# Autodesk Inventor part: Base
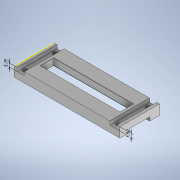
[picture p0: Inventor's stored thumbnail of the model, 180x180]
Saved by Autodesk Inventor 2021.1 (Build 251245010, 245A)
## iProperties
Created: 2020-12
Part Number: Base
Material: Generic
Document SubType Name: Modeling
Designer: BALA
Density: 1 g/cm^3
Appearance: Default
Author: BALA
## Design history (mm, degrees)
node "Annotations"
  node "Linear Dimension 1" dims "d4" = 10, "d5" = 60, "d6" = 4.5, "d7" = 10 (derived), "d87" = 5.25 (derived)
  node "Linear Dimension 2" dims "d4" = 10, "d5" = 60, "d6" = 4.5, "d7" = 10 (derived), "d88" = 5.5 (derived)
sketch "Sketch1"
  geometry: 1 further point
sketch "Sketch2"
  geometry: L1 (0, 0)-(160, 0); L2 (160, 0)-(160, 60); L3 (160, 60)-(0, 60); L4 (0, 60)-(0, 0)
  constraints: 8 end point, 2 parallel, 1 horizontal, 1 perpendicular
  dimensions: "d0" = 160 distance of L3.end L2.end; "d1" = 60 distance of L2.end L1.end
extrude "Extrusion1" new body sketch "Sketch2" distance "d2" = 15; taper "d3" = 0 deg
sketch "Sketch3"
  geometry: 1 further point
sketch "Sketch4"
  geometry: L1 (4.5, 0)-(14.5, 0); L2 (14.5, 0)-(14.5, 60); L3 (14.5, 60)-(4.5, 60); L4 (4.5, 60)-(4.5, 0); L5 (160, 60)-(0, 60) reference; L6 (80, 60)-(80, 0); L7 (0, 0)-(160, 0) reference; L8 (155.5, 0)-(145.5, 0); L9 (145.5, 0)-(145.5, 60); L10 (145.5, 60)-(155.5, 60); L11 (155.5, 60)-(155.5, 0)
  constraints: 18 end point, 4 symmetric about line, 2 midpoint, 2 parallel, 1 horizontal, 1 perpendicular
  dimensions: "d4" = 10 distance of L3.end L2.end; "d5" = 60 distance of L2.end L1.end; "d6" = 4.5 distance of L10.end L5.start; "d7" = 10 distance of L10.end L9.end (derived)
extrude "Extrusion2" cut sketch "Sketch4" distance "d8" = 5; taper "d9" = 0 deg
chamfer "Chamfer1" distance "d10" = 0.5; stored, may be unused: second distance "d11" = 2, angle "d12" = 45 deg
sketch "Sketch5"
  geometry: L1 (20, 20)-(20, 40); L2 (20, 40)-(140, 40); L3 (140, 40)-(140, 20); L4 (140, 20)-(20, 20); L5 (0, 60)-(0, 0) reference; L6 (160, 0)-(160, 60) reference
  constraints: 8 end point, 3 perpendicular, 1 vertical
  dimensions: "d13" = 20 distance from line of L1.end L5; "d17" = 20 distance from line of L6 L2.end; "d18" = 20 distance of L1.start L1.end
extrude "Extrusion3" cut sketch "Sketch5" distance "d19" = 15; taper "d20" = 0 deg
chamfer "Chamfer2" distance "d21" = 0.5; stored, may be unused: second distance "d22" = 2, angle "d23" = 45 deg
chamfer "Chamfer3" distance "d24" = 0.5; stored, may be unused: second distance "d25" = 2, angle "d26" = 45 deg
sketch "Sketch6"
  geometry: L1 (0, 60)-(0, 0) reference; L2 (0, 15)-(-160.097, 15); L3 (-160.097, 15)-(-160.097, 45); L4 (-160.097, 45)-(0, 45); L5 (0, 45)-(0, 15); 1 further point
  constraints: 8 end point, 2 parallel, 1 horizontal, 1 perpendicular, 1 point on line
  dimensions: "d27" = 15 distance of L2.start L1.end; "d28" = 15 distance of L4.end L1.start
extrude "Extrusion4" cut sketch "Sketch6" distance "d29" = 5.5; taper "d30" = 0 deg
sketch "Sketch7"
  geometry: L1 (0, 60)-(0, 0) reference
sketch "Sketch8"
  geometry: L1 (0, 60)-(0, 0) reference; L2 (-160, 60)-(0, 60) reference; L3 (-80, 60)-(-80, 0); L4 (0, 0)-(-160, 0) reference; L5 (-160, 15)-(-160, 45) reference; L6 (-160, 30)-(0, 30); C1 r 3.2 at (-10, 7.5); C2 r 3.2 at (-10, 52.5); C3 r 3.2 at (-150, 7.5); C4 r 3.2 at (-150, 52.5)
  constraints: 4 centre point, 4 end point, 4 midpoint, 3 symmetric about line, 3 other
  dimensions: "d33" = 6.4 diameter of C1
extrude "Extrusion5" cut sketch "Sketch8" distance "d34" = 15; taper "d35" = 0 deg
chamfer "Chamfer4" distance "d36" = 0.5; stored, may be unused: second distance "d37" = 2, angle "d38" = 45 deg
sketch "Sketch9"
  geometry: C1 r 3.7 at (-150, 7.5) reference; C2 r 4.25 at (-150, 7.5); C3 r 4.25 at (-150, 52.5); C4 r 4.25 at (-10, 7.5); 1 further point
  constraints: 3 centre point, 1 coincident
  dimensions: "d40" = 8.5 diameter of C2; "d42" = 8.5 diameter of C3; "d43" = 8.5 diameter of C4
sketch "Sketch10"
  geometry: 1 further point
sketch "Sketch11"
  geometry: C1 r 3.2 at (-10, 52.5) reference; C2 r 4.25 at (-10, 52.5); 1 further point
  constraints: 1 centre point, 1 coincident
  dimensions: "d44" = 8.5 diameter of C2
extrude "Extrusion6" cut sketch "Sketch9" distance "d45" = 4.5; taper "d46" = 0 deg
extrude "Extrusion7" cut sketch "Sketch11" distance "d47" = 4.5; taper "d48" = 0 deg
chamfer "Chamfer5" distance "d49" = 1; stored, may be unused: second distance "d50" = 2, angle "d51" = 45 deg
chamfer "Chamfer6" distance "d52" = 1; stored, may be unused: second distance "d53" = 2, angle "d54" = 45 deg
sketch "Sketch12"
  geometry: L1 (4.5, 0)-(4.5, 60) reference; L2 (14.5, 60)-(14.5, 0) reference; L3 (4.5, 0)-(14.5, 0); L4 (14.5, 0)-(14.5, 60); L5 (14.5, 60)-(4.5, 60); L6 (4.5, 60)-(4.5, 0); 3 further points
  constraints: 8 end point, 2 parallel, 1 horizontal, 1 perpendicular
sketch "Sketch13"
  geometry: 1 further point
extrude "Extrusion8" join sketch "Sketch12" distance "d55" = 4.5; taper "d56" = 0 deg
sketch "Sketch14"
  geometry: L1 (0, 0)-(4, 0) reference; L2 (160, 60)-(0, 60) reference; L3 (4, 0)-(14.997, 0); L4 (14.997, 0)-(14.997, 60); L5 (14.997, 60)-(4, 60); L6 (4, 60)-(4, 0); 1 further point
  constraints: 8 end point, 2 parallel, 1 horizontal, 1 perpendicular, 1 point on line
extrude "Extrusion9" join sketch "Sketch14" distance "d57" = 4.5; taper "d58" = 0 deg
sketch "Sketch15"
  geometry: L1 (0, 60)-(0, 0) reference; L2 (145, 60)-(15, 60) reference; L3 (0, 0)-(18.454, 0); L4 (18.454, 0)-(18.454, 60); L5 (18.454, 60)-(0, 60); L6 (0, 60)-(0, 0); 2 further points
  constraints: 8 end point, 2 parallel, 1 horizontal, 1 perpendicular, 1 point on line
extrude "Extrusion10" join sketch "Sketch15" distance "d59" = 4.5; taper "d60" = 0 deg
sketch "Sketch16"
  geometry: L1 (160, 60)-(0, 60) reference; L2 (5, 0)-(15, 0); L3 (15, 0)-(15, 60); L4 (15, 60)-(5, 60); L5 (5, 60)-(5, 0); 3 further points
  constraints: 8 end point, 2 parallel, 1 horizontal, 1 perpendicular
  dimensions: "d61" = 10 distance of L4.end L3.end
extrude "Extrusion11" cut sketch "Sketch16" distance "d62" = 4.5; taper "d63" = 0 deg
chamfer "Chamfer7" distance "d64" = 0.5; stored, may be unused: second distance "d65" = 2, angle "d66" = 45 deg
sketch "Sketch17"
  geometry: L1 (-15, 15)-(-15, 0) reference; L2 (-15, 15)-(0, 15); L3 (0, 15)-(0, 0); L4 (0, 0)-(-15, 0); L5 (-15, 0)-(-15, 15); 1 further point
  constraints: 8 end point, 2 parallel, 1 horizontal, 1 perpendicular
extrude "Extrusion12" join sketch "Sketch17" distance "d67" = 1; taper "d68" = 0 deg
sketch "Sketch18"
  geometry: L1 (5, 0)-(5, 60) reference; L2 (5, 0)-(15, 0); L3 (15, 0)-(15, 60); L4 (15, 60)-(5, 60); L5 (5, 60)-(5, 0); 2 further points
  constraints: 8 end point, 2 parallel, 1 horizontal, 1 perpendicular
extrude "Extrusion13" cut sketch "Sketch18" distance "d69" = 0.75; taper "d70" = 0 deg
sketch "Sketch19"
  geometry: L1 (145, 60)-(145, 0) reference; L2 (160, 60)-(156, 60) reference; L3 (145, 0)-(156, 0); L4 (156, 0)-(156, 60); L5 (156, 60)-(145, 60); L6 (145, 60)-(145, 0); 2 further points
  constraints: 8 end point, 2 parallel, 1 horizontal, 1 perpendicular
extrude "Extrusion14" join sketch "Sketch19" distance "d71" = 5; taper "d72" = 0 deg
sketch "Sketch20"
  geometry: L1 (160, 0)-(160, 60) reference; L2 (155, 0)-(145, 0); L3 (145, 0)-(145, 60); L4 (145, 60)-(155, 60); L5 (155, 60)-(155, 0); L6 (140.5, 19.5)-(140.5, 40.5) reference; L7 (140, 40)-(140, 20) reference; 1 further point
  constraints: 8 end point, 2 parallel, 1 horizontal, 1 perpendicular
  dimensions: "d73" = 10 distance of L3.end L4.end; "d74" = 19.5 distance from line of L6 L1.start (derived); "d75" = 5 distance between parallel lines of L3 L7 (derived); "d76" = 5 distance of L4.end L1.end
extrude "Extrusion15" cut sketch "Sketch20" distance "d77" = 5; taper "d78" = 0 deg
chamfer "Chamfer8" distance "d79" = 0.5; stored, may be unused: second distance "d80" = 2, angle "d81" = 45 deg
chamfer "Chamfer9" distance "d82" = 0.5; stored, may be unused: second distance "d83" = 2, angle "d84" = 45 deg
sketch "Sketch21"
  geometry: L1 (144.5, 0)-(145, 0) reference; L2 (145, 60)-(155, 60) reference; L3 (145, 0)-(155, 0); L4 (155, 0)-(155, 60); L5 (155, 60)-(145, 60); L6 (145, 60)-(145, 0); 2 further points
  constraints: 8 end point, 2 parallel, 1 horizontal, 1 perpendicular
extrude "Extrusion16" cut sketch "Sketch21" distance "d85" = 0.5; taper "d86" = 0 deg
body "Solid1"
